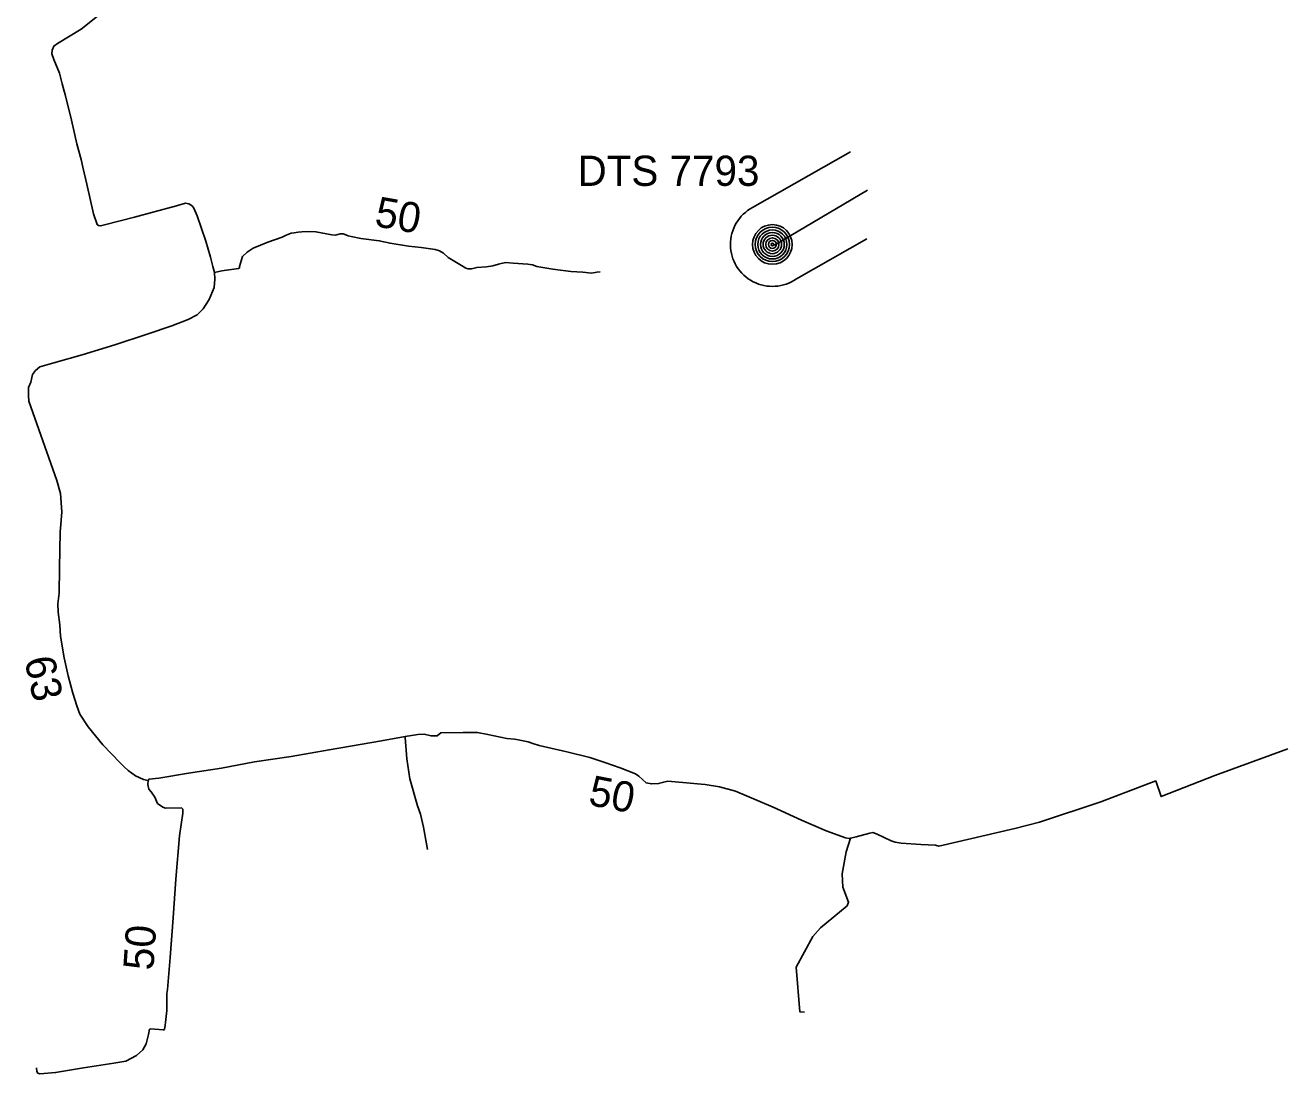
# Model space of a CAD drawing. Extents: x -444841 to -429545, y -1135312 to -1129851.
# Drawn here: x -441637.4 to -441303.1, y -1132645.4 to -1132367.9 of the extents above; entities that cross this region are included whole.
import ezdxf

# ---------------------------------------------------------------- set-up
doc = ezdxf.new("R2010")
doc.units = 0
for name, color, linetype in [('Vrstva 10', 7, 'Continuous'), ('Vrstva 11', 7, 'Continuous'), ('Vrstva 13', 7, 'Continuous'), ('Vrstva 15', 7, 'Continuous'), ('Vrstva 27', 7, 'Continuous'), ('Vrstva 30', 7, 'Continuous')]:
    doc.layers.add(name, color=color, linetype=linetype)

msp = doc.modelspace()

# ---------------------------------------------------------------- linework, layer by layer
at = {"layer": 'Vrstva 10'}
msp.add_lwpolyline([(-441414.37, -1132411.55), (-441439.03, -1132426.07)], dxfattribs=at)
at = {"layer": 'Vrstva 11'}
for radius in [5.25, 4.55, 3.85, 3.15, 2.45, 1.75, 1.05, 0.35]:
    msp.add_circle((-441439.58, -1132425.92), radius, dxfattribs=at)
at = {"layer": 'Vrstva 15'}
for points in [[(-441418.93, -1132401.38), (-441444.83, -1132416.14)], [(-441433.23, -1132435.02), (-441414.59, -1132424.45)]]:
    msp.add_lwpolyline(points, dxfattribs=at)
msp.add_arc((-441439.58, -1132425.92), 11.1, 118.2404, 304.8832, dxfattribs=at)
at = {"layer": 'Vrstva 27'}
for points in [[(-441587.3, -1132433.32), (-441587.7, -1132431.76), (-441588.36, -1132429.27), (-441589.62, -1132425.07), (-441591.86, -1132418.31), (-441592.74, -1132416.31), (-441593.2, -1132415.72), (-441594.06, -1132415.15), (-441595.01, -1132415.03), (-441597.35, -1132415.67), (-441603.27, -1132417.31), (-441608.48, -1132418.71), (-441616.46, -1132420.74), (-441617.47, -1132421.02), (-441618.04, -1132420.95), (-441618.4, -1132420.66), (-441619.29, -1132417.86), (-441621.14, -1132409.98), (-441622.17, -1132405.45), (-441622.6, -1132403.42), (-441623.24, -1132401.27), (-441623.73, -1132399.33), (-441625.12, -1132393.01), (-441626.86, -1132386.21), (-441627.1, -1132385.33), (-441627.61, -1132383.4), (-441628.36, -1132380.63), (-441629.87, -1132376.96), (-441630.33, -1132375.45), (-441630.31, -1132374.49), (-441629.8, -1132373.44), (-441628.83, -1132372.71), (-441622.64, -1132368.96), (-441616.93, -1132364.46)], [(-441587.3, -1132433.32), (-441585.34, -1132432.92), (-441580.93, -1132432.26), (-441580.75, -1132432.22), (-441580.63, -1132432.13), (-441580.63, -1132431.73), (-441580.15, -1132429.97), (-441579.84, -1132429.08), (-441578.67, -1132428), (-441577.07, -1132426.94), (-441573.13, -1132425.32), (-441569.4, -1132423.95), (-441568.28, -1132423.43), (-441566.99, -1132422.94), (-441566.17, -1132422.82), (-441565.18, -1132422.68), (-441564.18, -1132422.6), (-441562.49, -1132422.46), (-441560.44, -1132422.58), (-441556.2, -1132423.36), (-441555.27, -1132423.46), (-441554.01, -1132423.11), (-441553.22, -1132423.11), (-441552.56, -1132423.35), (-441551.86, -1132423.6), (-441551.1, -1132423.81), (-441548.58, -1132424.31), (-441543.66, -1132424.95), (-441540.81, -1132425.6), (-441535.89, -1132426.35), (-441532.53, -1132426.7), (-441528.9, -1132427.27), (-441527.73, -1132427.63), (-441526.64, -1132428.22), (-441525.46, -1132429.35), (-441521.89, -1132431.53), (-441520.73, -1132432.17), (-441520.12, -1132432.35), (-441519.26, -1132432.37), (-441517.8, -1132432.01), (-441515.31, -1132431.86), (-441513.56, -1132431.62), (-441512.09, -1132431.13), (-441510.2, -1132430.71), (-441508.24, -1132430.87), (-441504.36, -1132431.1), (-441503.11, -1132431.35), (-441501.99, -1132431.77), (-441497.73, -1132432.42), (-441492.96, -1132433.06), (-441489.77, -1132433.22), (-441487.5, -1132433.48), (-441486.04, -1132433.24), (-441485.14, -1132433.13)], [(-441627.98, -1132500), (-441627.72, -1132496.68), (-441628.05, -1132491.82), (-441629.07, -1132488.41), (-441636.47, -1132467.35), (-441636.55, -1132465.87), (-441636.56, -1132463.78), (-441635.95, -1132462.37), (-441635.5, -1132460.35), (-441634.66, -1132459.26), (-441633.58, -1132458.33), (-441629.87, -1132457.28), (-441622.37, -1132455.14), (-441613.69, -1132452.51), (-441605.13, -1132449.68), (-441598.6, -1132447.42), (-441594.3, -1132445.74), (-441591.85, -1132444.58), (-441590.31, -1132443), (-441588.68, -1132440.52), (-441587.35, -1132437.27), (-441587.17, -1132435.1), (-441587.3, -1132433.32)], [(-441611.21, -1132564.13), (-441611.96, -1132563.48), (-441612.28, -1132563.12), (-441616.88, -1132558.35), (-441620.78, -1132553.57), (-441622.97, -1132550.24), (-441623.72, -1132548.03), (-441624.76, -1132544.67), (-441626.04, -1132540.11), (-441627.11, -1132535.34), (-441628.06, -1132529.62), (-441628.21, -1132526.59), (-441628.73, -1132523.26), (-441628.75, -1132520.98), (-441628.46, -1132518.16), (-441628.37, -1132511.55), (-441628.13, -1132502), (-441627.98, -1132500)], [(-441395.47, -1132585.13), (-441396.38, -1132584.88), (-441400.29, -1132584.74), (-441405.45, -1132584.38), (-441407.07, -1132584.12), (-441408.12, -1132583.78), (-441411.82, -1132581.95), (-441413.01, -1132581.55), (-441413.79, -1132581.69), (-441417.35, -1132582.65), (-441419.28, -1132583.1), (-441420.24, -1132582.97), (-441425.36, -1132581.09), (-441431.86, -1132578.27), (-441439.36, -1132574.81), (-441446.46, -1132571.83), (-441449.31, -1132570.62), (-441453.56, -1132569.44), (-441457.38, -1132568.8), (-441458.41, -1132568.71), (-441460.4, -1132568.55), (-441467.27, -1132567.97), (-441468.34, -1132568.18), (-441469.71, -1132568.58), (-441471.62, -1132568.68), (-441473.01, -1132568.41), (-441474.92, -1132566.63), (-441475.78, -1132565.97), (-441479.88, -1132564.4), (-441483.94, -1132563.04), (-441487.89, -1132561.71), (-441494.04, -1132560.19), (-441501.32, -1132558.55), (-441502.97, -1132557.97), (-441504.28, -1132557.56), (-441507.3, -1132556.93), (-441507.85, -1132556.87), (-441509.88, -1132556.67), (-441514.93, -1132555.57), (-441517.63, -1132555.1), (-441521.46, -1132555.08), (-441527.34, -1132555.2), (-441528.38, -1132555.93), (-441529.96, -1132555.99), (-441531.76, -1132555.53), (-441533.45, -1132555.64), (-441536.8, -1132556.15), (-441543.04, -1132557.24), (-441556.96, -1132559.64), (-441566.97, -1132561.39), (-441576.68, -1132562.87), (-441585.47, -1132564.48), (-441594.2, -1132565.83), (-441602.04, -1132567.12), (-441604.61, -1132567.4), (-441604.86, -1132567.77)], [(-441530.92, -1132586.04), (-441531.15, -1132584.51), (-441531.94, -1132580.11), (-441532.78, -1132576.71), (-441533.53, -1132574.52), (-441535.56, -1132567.3), (-441536.38, -1132562.08), (-441536.79, -1132556.43), (-441536.8, -1132556.15)], [(-441303.12, -1132559.41), (-441322.45, -1132566.42), (-441336.67, -1132572.03), (-441338.05, -1132567.89)], [(-441604.86, -1132567.77), (-441606.13, -1132567.51), (-441608.18, -1132566.55), (-441610.15, -1132565.12), (-441611.21, -1132564.13)], [(-441600.36, -1132632.53), (-441600.28, -1132631.78), (-441599.95, -1132628.61), (-441599.91, -1132624.1), (-441599.73, -1132623.09), (-441599.05, -1132614.61), (-441598.25, -1132604.15), (-441597.56, -1132593.84), (-441596.55, -1132582.41), (-441595.68, -1132576.45), (-441595.64, -1132575.4), (-441596.07, -1132575.03), (-441600.24, -1132575.06), (-441601.01, -1132574.84), (-441602.38, -1132573.83), (-441603.11, -1132572.17), (-441604.04, -1132570.75), (-441604.69, -1132570.04), (-441604.91, -1132568.84), (-441604.86, -1132567.77)], [(-441338.05, -1132567.89), (-441352.65, -1132573.42), (-441368.83, -1132578.81), (-441375.42, -1132580.44), (-441395.47, -1132585.13)], [(-441418.89, -1132583.01), (-441420.07, -1132586.64), (-441421.1, -1132592.48), (-441420.94, -1132596.03), (-441419.42, -1132599.94), (-441419.82, -1132600.9), (-441426.86, -1132606.73), (-441428.85, -1132609.07), (-441433.26, -1132617.17), (-441432.35, -1132628.99), (-441431.11, -1132629.1)], [(-441600.36, -1132632.53), (-441600.57, -1132633.64), (-441600.73, -1132633.78), (-441600.92, -1132633.76), (-441604.18, -1132633.5), (-441604.47, -1132633.59), (-441604.76, -1132635.03), (-441605.41, -1132637.46), (-441606.29, -1132639.06), (-441607.91, -1132640.53), (-441610.74, -1132642.07), (-441613.99, -1132642.6), (-441621.95, -1132643.77), (-441629.38, -1132645.08), (-441633.57, -1132645.37), (-441634.09, -1132645.22), (-441634.32, -1132644.78), (-441634.4, -1132643.84)]]:
    msp.add_lwpolyline(points, dxfattribs=at)

# ---------------------------------------------------------------- texts
at = {"layer": 'Vrstva 13'}
msp.add_text('DTS 7793', height=8, dxfattribs=at).set_placement((-441491.17, -1132410.42))
at = {"layer": 'Vrstva 30'}
for s, rotation, p in [('50', 349.9291, (-441545.17, -1132421.04)), ('63', 282.6432, (-441637.7, -1132535.76)), ('50', 349.0075, (-441488.58, -1132574.18)), ('50', 86.1767, (-441603.49, -1132618.15))]:
    msp.add_text(s, height=8, rotation=rotation, dxfattribs=at).set_placement(p)

doc.saveas('drawing.dxf')
